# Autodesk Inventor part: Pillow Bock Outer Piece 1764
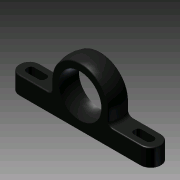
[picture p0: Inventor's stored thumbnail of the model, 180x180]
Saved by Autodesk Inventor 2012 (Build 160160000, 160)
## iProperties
Created: 2009-01
Part Number: Pillow Bock Outer Piece 1764
Document SubType Name: Modeling
Designer: lwoods
Density: 1.4 g/cm^3
Material: PVC-Piping
Mass: 16.083 g
Surface Area: 61.8162 cm^2
Volume: 11.4879 cm^3
Author: lwoods
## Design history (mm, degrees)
sketch "Sketch1"
  geometry: L1 (106.919, -24.218)-(106.919, -34.759); L2 (106.919, -34.759)-(21.575, -34.759); L3 (21.575, -34.759)-(21.575, -24.218); L4 (55.774, -29.552)-(75.813, -29.552); L5 (64.247, -16.738)-(64.247, -29.552); L6 (21.575, -24.218)-(53.842, -24.218); L7 (74.651, -24.218)-(106.919, -24.218); L8 (46.276, -16.738)-(46.276, -24.218); L9 (82.217, -16.738)-(82.217, -24.218); L10 (64.247, 1.233)-(64.247, -34.759); A1 r 12.814 centre (64.247, -16.738) between (64.247, -3.924) and (74.651, -24.218); A2 r 17.971 centre (64.247, -16.738) between (64.247, 1.233) and (82.217, -16.738)
  constraints: 20 end point, 7 point on circle, 6 perpendicular, 3 parallel, 3 point on line, 2 centre point, 2 horizontal, 2 tangent, 1 coincident, 1 midpoint
  dimensions: "d0" = 10.541 distance of L1.start L1.end; "d1" = 85.344 distance of L1.end L2.end; "d2" = 42.672 distance from line of L1 L5.start; "d3" = 5.207 distance between parallel lines of L2 L4; "d4" = 0 distance from line of L4 L5.end; "d5" = 12.8143 distance of L5.start L5.end; "d6" = 35.941 diameter of A2
extrude "Extrusion2" new body sketch "Sketch1" stored distance "d12" = 12.192; taper "d13" = 0 deg
revolve "Revolution1" stored, may be unused: angle "d14" = 90 deg
sketch "Sketch2"
  geometry: L1 (0, 0)-(85.344, 0); L2 (85.344, 0)-(85.344, -12.192); L3 (85.344, -12.192)-(0, -12.192); L4 (0, -12.192)-(0, 0); L5 (0, 0)-(87.475, 0); L6 (87.475, 0)-(87.475, 19.156); L7 (87.475, 19.156)-(0, 19.156); L8 (0, 19.156)-(0, 0); L9 (0, -12.192)-(88.547, -12.192); L10 (88.547, -12.192)-(88.547, -30.812); L11 (88.547, -30.812)-(0, -30.812); L12 (0, -30.812)-(0, -12.192)
  constraints: 24 end point, 6 parallel, 3 horizontal, 3 perpendicular
extrude "Extrusion3" cut sketch "Sketch2" distance "d15" = 127; taper "d16" = 0 deg
sketch "Sketch3"
  geometry: L1 (55.815, -24.218)-(53.842, -24.218) reference; L2 (74.651, -24.218)-(72.678, -24.218) reference; C1 r 12.814 at (64.247, -16.738); A1 r 12.814 centre (64.247, -16.738) between (53.842, -24.218) and (74.651, -24.218) reference; A2 r 11.271 centre (64.247, -16.738) between (72.678, -24.218) and (55.815, -24.218) reference; A3 r 16.905 centre (64.247, -16.738) between (81.152, -16.738) and (47.342, -16.738) reference
  constraints: 1 centre point, 1 coincident, 1 concentric
extrude "Extrusion4" cut sketch "Sketch3" distance "d17" = 127; taper "d18" = 0 deg
fillet "Fillet4" dims "d19" = 2.54
fillet "Fillet5" dims "d20" = 6.096
sketch "Sketch4"
  geometry: L1 (-36.576, -6.096)-(-19.584, -6.096) reference; L2 (-19.584, 6.096)-(-36.576, 6.096) reference; L3 (-37.353, 2.451)-(-27.493, 2.451); L4 (-27.493, 2.451)-(-27.493, -2.451); L5 (-27.493, -2.451)-(-37.353, -2.451); L6 (-37.353, -2.451)-(-37.353, 2.451); L7 (-37.353, 0)-(-38.227, 0); L8 (-38.227, 0)-(-42.672, 0); L9 (-27.493, 0)-(-26.619, 0); L10 (-16.905, -6.096)-(16.905, -6.096) reference; L11 (16.905, 6.096)-(-16.905, 6.096) reference; L12 (0, 6.096)-(0, -6.096); L13 (37.353, 2.451)-(27.493, 2.451); L14 (27.493, -2.451)-(37.353, -2.451); C1 r 3.175 at (-31.191, 0); C2 r 3.175 at (31.191, 0); A1 r 6.096 centre (-36.576, 0) between (-36.576, 6.096) and (-36.576, -6.096) reference; A2 r 20.51 centre (0, 0) between (-19.584, 6.096) and (-19.584, -6.096) reference; A3 r 3.873 centre (-34.354, 0) between (-37.353, 2.451) and (-37.353, -2.451); A4 r 6.096 centre (-36.576, 0) between (-36.576, 6.096) and (-36.576, -6.096) reference; A5 r 3.873 centre (-30.493, 0) between (-27.493, -2.451) and (-27.493, 2.451); A6 r 17.97 centre (0, 0) between (16.905, -6.096) and (16.905, 6.096) reference; A7 r 17.97 centre (0, 0) between (-16.905, 6.096) and (-16.905, -6.096) reference; A8 r 3.873 centre (30.493, 0) between (27.493, 2.451) and (27.493, -2.451); A9 r 3.873 centre (34.353, 0) between (37.353, -2.451) and (37.353, 2.451)
  constraints: 20 end point, 11 point on circle, 7 symmetric about line, 6 centre point, 4 midpoint, 2 parallel, 2 tangent, 1 equal radius, 1 horizontal, 1 perpendicular, 3 other
  dimensions: "d21" = 4.9022 distance of L3.end L4.end; "d22" = 3.6449 distance between parallel lines of L2 L3; "d23" = 4.445 distance of L7.end L8.end; "d24" = 11.6078 distance of L9.end L7.end; "d36" = 6.35 diameter of C1
extrude "Extrusion5" cut sketch "Sketch4" distance "d25" = 127; taper "d26" = 0 deg
fillet "Fillet6" dims "d27" = 2.032
fillet "Fillet7" dims "d28" = 0.635
workplane "Work Plane1"
  workaxis "Work Axis1"
sketch "Sketch5"
  geometry: L1 (-5.661, 0)-(-5.661, 0) reference; L2 (-5.661, 0)-(5.661, 0) reference; L3 (5.661, 0)-(5.661, 0) reference; L4 (5.661, 0)-(-5.661, 0) reference; L5 (-9.563, 10.935)-(9.563, 10.935); L6 (9.563, 10.935)-(9.563, 7.938); L7 (9.563, 7.938)-(-9.563, 7.938); L8 (-9.563, 7.938)-(-9.563, 10.935); L9 (0, 10.935)-(0, 14.11); L10 (-6.096, 8.115)-(6.096, 8.115) reference; L11 (-6.096, 8.115)-(-6.096, 18.021) reference; L12 (-6.096, 18.021)-(6.096, 18.021) reference; L13 (6.096, 18.021)-(6.096, 8.115) reference; L14 (0, 18.021)-(0, 17.186); L15 (-13.388, 0)-(13.388, 0) reference; A1 r 15.99 centre (0, -1.88) between (9.563, 10.935) and (-9.563, 10.935)
  constraints: 12 end point, 3 parallel, 3 point on circle, 2 midpoint, 1 centre point, 1 horizontal, 1 perpendicular
  dimensions: "d30" = 3.175 distance of L9.start L9.end; "d31" = 2.9972 distance of L7.end L5.start; "d32" = 19.1262 distance of L6.end L7.end; "d33" = 7.9375 distance between parallel lines of L7 L2; "d34" = 0 distance between parallel lines of L14 L9
revolve "Revolution2" sketch "Sketch5" stored, may be unused: angle "d35" = 90 deg
body "Solid1"
node "Projected Loop1"
node "Projected Loop2"
node "Projected Loop3"
node "Projected Loop4"
other parameters: "d29" = 90 deg
